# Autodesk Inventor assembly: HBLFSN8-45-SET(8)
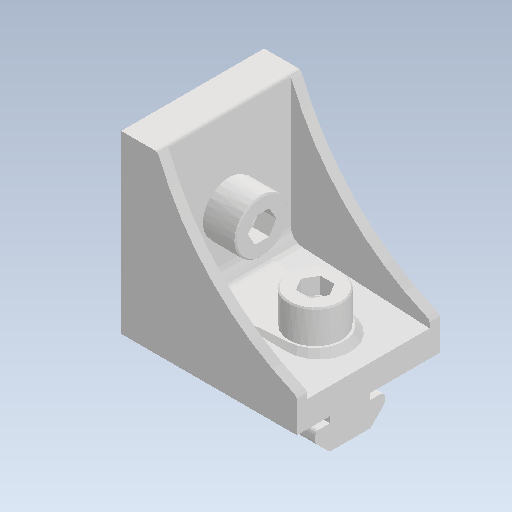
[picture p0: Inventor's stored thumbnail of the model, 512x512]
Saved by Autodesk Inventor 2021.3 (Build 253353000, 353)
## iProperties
Created: 2022-02
Part Number: HBLFSN8-45-SET(8)
Document SubType Name: Assembly
Designer: kengo
Author: kengo
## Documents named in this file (4)
- C:\Users\kengo\Documents\S2S_frame\SDC345\frame_misumi_ver12\HBLFSN8-45-SET(8).iam
- C:\Users\kengo\Documents\S2S_frame\SDC345\frame_misumi_ver12\HBLFSN8-45.ipt
- C:\Users\kengo\Documents\S2S_frame\SDC345\frame_misumi_ver12\HNTT8-8.ipt
- C:\Users\kengo\Documents\S2S_frame\SDC345\frame_misumi_ver12\CBM8-20.ipt
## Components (5 placed, 3 different names)
1. HBLFSN8-45
2. HNTT8-8
3. CBM8-20
4. HNTT8-8:1
5. CBM8-20:1
